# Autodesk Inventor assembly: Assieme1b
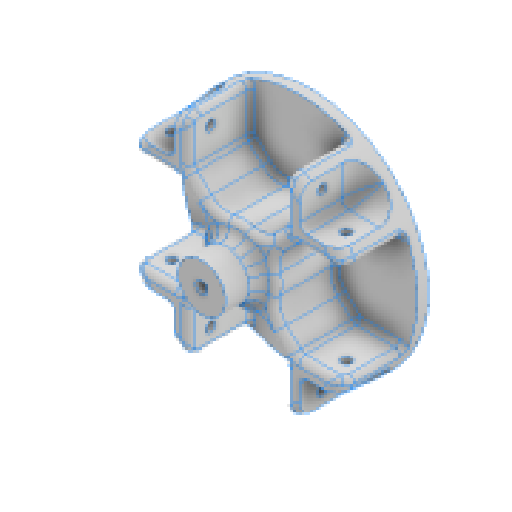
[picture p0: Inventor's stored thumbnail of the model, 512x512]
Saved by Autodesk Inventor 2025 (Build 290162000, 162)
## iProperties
Created: 2025-05
Part Number: Assieme1b
Document SubType Name: Assembly
Designer: R5800u
Author: R5800u
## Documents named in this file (2)
- C:\Users\R5800u\Desktop\mecanum4\Assieme1b.iam
- C:\Users\R5800u\Desktop\mecanum4\Parte1.ipt
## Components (1 placed, 1 different names)
1. Parte1:1
